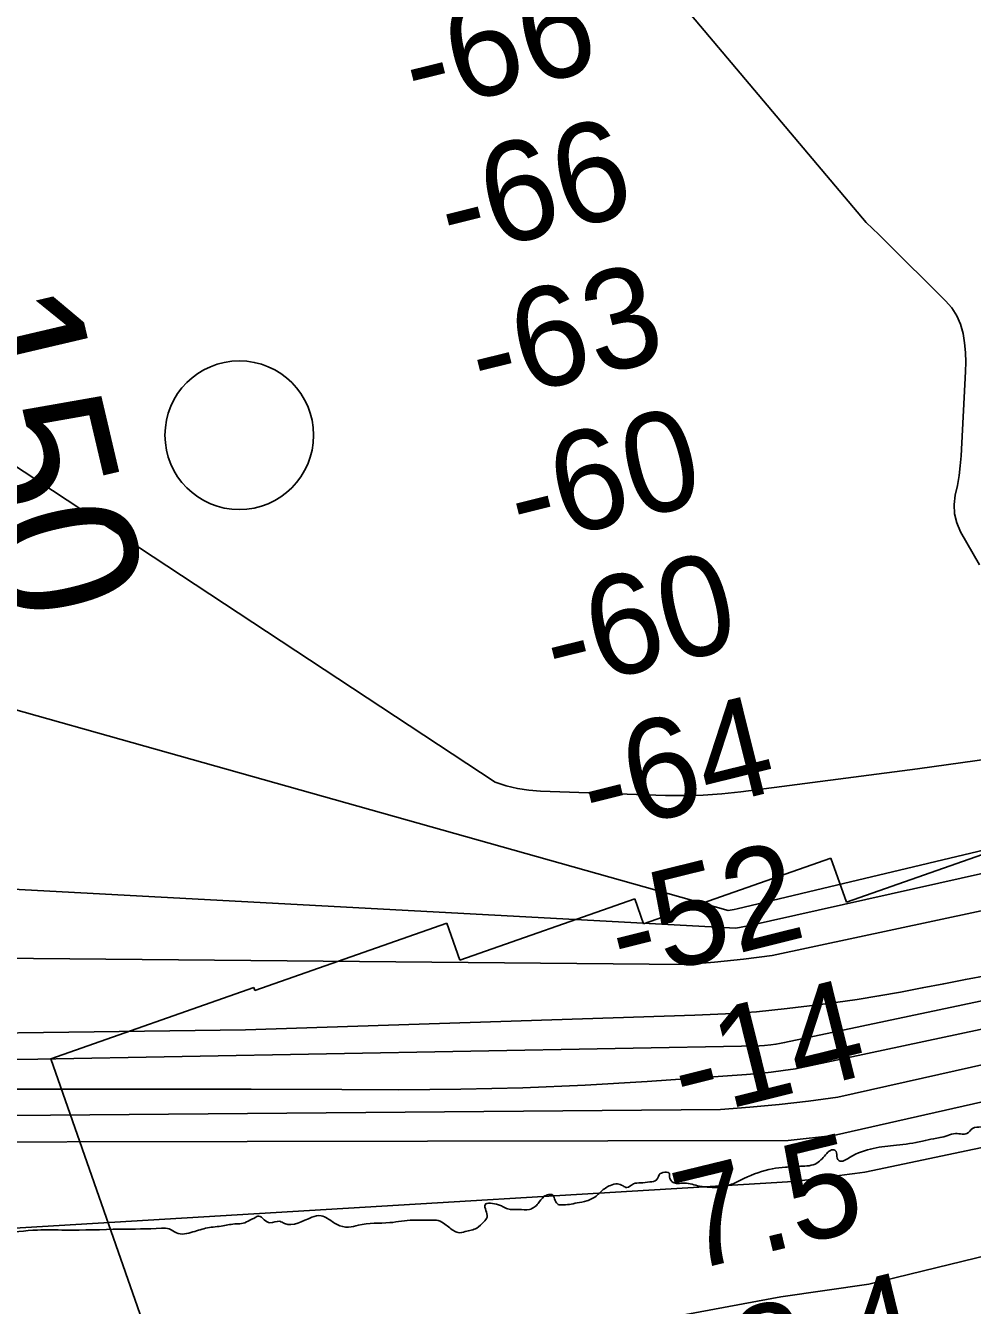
# Model space of a CAD drawing. Extents: x 3445503 to 3483459, y 540493 to 566012.
# Drawn here: x 3472232 to 3472869, y 549843 to 550704 of the extents above; entities that cross this region are included whole.
import ezdxf

# ---------------------------------------------------------------- set-up
doc = ezdxf.new("R2010")
doc.units = 0
for name, color, linetype in [('V-CHAN-NAID', 7, 'Continuous'), ('V-RIVR-EDGE', 7, 'Continuous'), ('V-RIVR-IDEN', 7, 'Continuous'), ('V-RIVR-MILE', 7, 'Continuous'), ('V-RIVR-RANG', 7, 'Continuous'), ('V-RRAP-RVMT', 7, 'Continuous'), ('V-TOPO-DPTH', 7, 'Continuous'), ('V-TOPO-MAJR', 7, 'Continuous'), ('V-TOPO-MINR', 7, 'Continuous'), ('V-TOPO-WATR', 7, 'Continuous')]:
    doc.layers.add(name, color=color, linetype=linetype)

msp = doc.modelspace()

# ---------------------------------------------------------------- linework, layer by layer
at = {"layer": 'V-RIVR-EDGE'}
msp.add_spline([(3473267.48, 550050.53), (3473262.79, 550050.71), (3473261.4, 550049.33), (3473261.38, 550045.15), (3473259.64, 550043.07), (3473258.26, 550045.51), (3473257.22, 550048.29), (3473255.14, 550048.99), (3473250.27, 550049.01), (3473240.53, 550046.25), (3473232.88, 550045.23), (3473226.97, 550045.94), (3473221.41, 550044.56), (3473208.19, 550041.11), (3473186.97, 550035.95), (3473184.19, 550035.96), (3473182.8, 550036.66), (3473178.28, 550036.67), (3473175.84, 550034.94), (3473172.71, 550034.25), (3473168.89, 550034.61), (3473164.37, 550034.27), (3473158.45, 550032.2), (3473148.02, 550030.83), (3473146.28, 550029.8), (3473145.23, 550028.41), (3473143.49, 550026.33), (3473141.4, 550025.64), (3473141.06, 550028.07), (3473137.24, 550029.47), (3473116.03, 550025.35), (3473100.03, 550021.91), (3473109.07, 550023.98), (3473098.98, 550020.53), (3473094.46, 550019.5), (3473091.68, 550019.15), (3473086.81, 550018.12), (3473072.2, 550015.38), (3473050.29, 550012.3), (3473043.68, 550010.58), (3473029.77, 550008.18), (3473028.73, 550008.88), (3473024.56, 550008.54), (3473009.6, 550004.76), (3472996.72, 549998.88), (3472990.11, 549995.07), (3472986.28, 549994.04), (3472984.9, 549996.13), (3472982.12, 549996.13), (3472970.98, 549992.34), (3472959.85, 549989.24), (3472952.2, 549988.21), (3472948.72, 549988.22), (3472946.63, 549986.49), (3472943.84, 549983.02), (3472940.36, 549980.59), (3472933.06, 549979.92), (3472926.1, 549978.2), (3472910.45, 549974.41), (3472893.06, 549969.24), (3472887.14, 549966.12), (3472884, 549963.35), (3472881.22, 549963.71), (3472874.96, 549963.03), (3472869.05, 549962), (3472865.22, 549958.53), (3472862.09, 549958.19), (3472857.57, 549958.55), (3472852.35, 549957.17), (3472847.13, 549955.79), (3472842.96, 549955.11), (3472835.31, 549953.39), (3472817.92, 549950.65), (3472786.27, 549942.39), (3472779.31, 549940.32), (3472777.92, 549942.06), (3472777.24, 549946.58), (3472775.15, 549947.63), (3472772.02, 549946.25), (3472770.98, 549945.21), (3472764.36, 549938.62), (3472753.23, 549936.56), (3472743.14, 549935.89), (3472734.45, 549934.87), (3472715.31, 549928.31), (3472708.01, 549924.85), (3472698.96, 549922.44), (3472692.36, 549922.46), (3472685.4, 549923.17), (3472675.33, 549925.28), (3472670.81, 549924.94), (3472667.68, 549925.65), (3472665.26, 549929.48), (3472664.92, 549931.91), (3472660.75, 549932.27), (3472659.01, 549931.58), (3472656.56, 549927.41), (3472652.04, 549926.03), (3472645.78, 549925.35), (3472640.91, 549924.67), (3472636.39, 549922.25), (3472633.96, 549923.3), (3472630.14, 549924.7), (3472625.61, 549923.67), (3472622.13, 549921.94), (3472616.56, 549917.08), (3472609.6, 549913.28), (3472602.99, 549911.9), (3472592.56, 549910.54), (3472589.78, 549911.24), (3472585.97, 549917.51), (3472583.88, 549917.51), (3472580.75, 549916.13), (3472576.92, 549911.62), (3472571, 549907.46), (3472563.7, 549907.48), (3472556.4, 549907.85), (3472552.92, 549909.59), (3472550.15, 549910.64), (3472541.11, 549910.66), (3472542.48, 549902.32), (3472540.38, 549899.19), (3472535.51, 549895.03), (3472527.85, 549892.62), (3472522.98, 549891.94), (3472519.86, 549893.34), (3472513.27, 549898.22), (3472508.4, 549900.32), (3472504.58, 549900.33), (3472492.76, 549900.35), (3472477.11, 549898.66), (3472455.9, 549896.97), (3472449.29, 549895.6), (3472441.65, 549897.35), (3472435.06, 549901.54), (3472430.89, 549903.29), (3472424.63, 549902.26), (3472406.19, 549898.14), (3472403.07, 549899.53), (3472396.46, 549898.51), (3472392.64, 549900.6), (3472388.83, 549903.05), (3472386.39, 549902.01), (3472382.91, 549900.28), (3472378.38, 549898.2), (3472373.86, 549897.87), (3472364.82, 549896.5), (3472354.39, 549895.13), (3472344.65, 549892.38), (3472333.52, 549891.71), (3472328.66, 549894.5), (3472323.45, 549894.86), (3472295.64, 549894.24), (3472258.79, 549893.63), (3472240.02, 549893.68), (3472214.98, 549891.31), (3472201.42, 549889.95), (3472194.46, 549888.58), (3472186.47, 549888.95), (3472180.57, 549892.78), (3472173.97, 549894.19), (3472164.58, 549894.21), (3472142.68, 549894.62), (3472134.68, 549893.94), (3472115.91, 549892.25), (3472099.57, 549892.64), (3472079.06, 549891.99), (3472074.2, 549895.48), (3472067.95, 549898.62), (3472059.26, 549898.65), (3472042.57, 549898.34), (3472034.23, 549898.36), (3472025.19, 549899.77), (3472021.37, 549901.17), (3472015.12, 549901.54), (3472000.87, 549902.27), (3471998.43, 549901.58), (3471996.34, 549899.15), (3471992.86, 549897.42), (3471989.74, 549901.6), (3471986.96, 549901.95), (3471978.96, 549901.63), (3471972.7, 549900.6), (3471966.79, 549900.61), (3471957.4, 549898.55), (3471951.84, 549897.52), (3471943.49, 549896.85), (3471929.59, 549896.19), (3471925.41, 549895.5), (3471920.54, 549892.38), (3471918.79, 549889.26), (3471914.62, 549887.18), (3471909.05, 549887.2), (3471906.28, 549890.33), (3471902.12, 549893.82), (3471877.78, 549893.53), (3471874.99, 549890.06), (3471872.21, 549887.98), (3471868.38, 549886.95), (3471863.86, 549887.31), (3471857.96, 549889.76), (3471851.7, 549890.47), (3471841.27, 549889.45), (3471833.28, 549889.47), (3471826.33, 549891.92), (3471821.47, 549894.37), (3471818.68, 549892.98), (3471815.55, 549891.6), (3471812.42, 549888.48), (3471807.88, 549883.62), (3471803.7, 549879.81), (3471798.83, 549879.13), (3471794.67, 549881.92), (3471789.48, 549891.32), (3471784.27, 549895.5), (3471778.72, 549896.56), (3471759.95, 549900.43), (3471750.92, 549904.27), (3471745.71, 549905.33), (3471738.4, 549900.48), (3471734.92, 549898.06), (3471725.87, 549896.34), (3471684.85, 549896.44)], degree=3, dxfattribs=at)
at = {"layer": 'V-RIVR-MILE'}
msp.add_circle((3472375.81, 550428.15), 50, dxfattribs=at)
at = {"layer": 'V-RRAP-RVMT'}
for p, q in [((3472784.2, 550114.21), (3472906.99, 550157.21)), ((3472647.79, 550099.5), (3472773.84, 550143.76)), ((3472773.84, 550143.76), (3472784.2, 550114.21)), ((3472524.26, 550075.16), (3472641.82, 550116.34)), ((3472641.82, 550116.34), (3472647.79, 550099.5)), ((3472386.21, 550054.83), (3472515.5, 550100.12)), ((3472515.5, 550100.12), (3472524.26, 550075.16)), ((3472249.04, 550008.89), (3472385.49, 550056.81)), ((3472385.49, 550056.81), (3472386.21, 550054.83)), ((3472416.68, 549530.16), (3472249.04, 550008.89))]:
    msp.add_line(p, q, dxfattribs=at)
at = {"layer": 'V-TOPO-DPTH'}
for points in [[(3471527.3, 550203.44), (3471721.65, 550155.04), (3471725.84, 550154.05), (3471730.04, 550153.13), (3471734.26, 550152.32), (3471738.49, 550151.57), (3471742.74, 550150.91), (3471747, 550150.29), (3471751.26, 550149.73), (3471755.53, 550149.21), (3471756.08, 550149.15), (3471760.62, 550148.63), (3471765.17, 550148.11), (3471769.71, 550147.59), (3471774.26, 550147.06), (3472709.72, 550096.65), (3472718.14, 550098.12), (3473740.18, 550326.75)], [(3473740.18, 550326.75), (3472718.14, 550098.12), (3472709.72, 550096.65), (3471774.26, 550147.06), (3471769.71, 550147.59), (3471765.17, 550148.11), (3471760.62, 550148.63), (3471756.08, 550149.15), (3471755.53, 550149.21), (3471751.26, 550149.73), (3471747, 550150.29), (3471742.74, 550150.91), (3471738.49, 550151.57), (3471734.26, 550152.32), (3471730.04, 550153.13), (3471725.84, 550154.05), (3471721.65, 550155.04), (3471527.3, 550203.44)], [(3473778.31, 550301.21), (3472734.35, 550078.36), (3472714.95, 550075.72), (3472695.49, 550073.71), (3472675.97, 550072.12), (3471798.63, 550080.29), (3471782.69, 550082.03), (3471766.76, 550083.77), (3471750.81, 550085.5), (3471734.87, 550087.21), (3471589.23, 550102.82), (3471500.51, 550112.74)], [(3473778.31, 550301.21), (3472734.35, 550078.36), (3472714.95, 550075.72), (3472695.49, 550073.71), (3472675.97, 550072.12), (3471798.63, 550080.29), (3471782.69, 550082.03), (3471766.76, 550083.77), (3471750.81, 550085.5), (3471734.87, 550087.21), (3471589.23, 550102.82), (3471500.51, 550112.74)], [(3473773.74, 550257.36), (3472893.34, 550067.65), (3472878.79, 550064.94), (3472864.25, 550062.17), (3472849.72, 550059.34), (3472835.21, 550056.47), (3472820.67, 550053.69), (3472806.11, 550051.1), (3472791.5, 550048.78), (3472776.86, 550046.65), (3472764.97, 550045.04), (3472744.33, 550042.55), (3472723.66, 550040.49), (3472702.93, 550039.07), (3472682.17, 550038.08), (3472379.93, 550028.25), (3472074.04, 550024.36)], [(3472074.04, 550024.36), (3472379.93, 550028.25), (3472682.17, 550038.08), (3472702.93, 550039.07), (3472723.66, 550040.49), (3472744.33, 550042.55), (3472764.97, 550045.04), (3472776.86, 550046.65), (3472791.5, 550048.78), (3472806.11, 550051.1), (3472820.67, 550053.69), (3472835.21, 550056.47), (3472849.72, 550059.34), (3472864.25, 550062.17), (3472878.79, 550064.94), (3472893.34, 550067.65), (3473773.74, 550257.36)], [(3472200.98, 549988.31), (3472261.93, 549988.39), (3472322.88, 549988.4), (3472383.83, 549988.31), (3472444.78, 549988.15), (3472483.03, 549988.02), (3472524.84, 549988.34), (3472566.63, 549989.28), (3472608.39, 549991.14), (3472650.13, 549993.61), (3472716.98, 549998.31), (3472725.27, 549999.01), (3472733.53, 549999.86), (3472741.77, 550000.93), (3472749.99, 550002.15), (3473790.16, 550223.51)], [(3473790.16, 550223.51), (3472749.99, 550002.15), (3472741.77, 550000.93), (3472733.53, 549999.86), (3472725.27, 549999.01), (3472716.98, 549998.31), (3472650.13, 549993.61), (3472608.39, 549991.14), (3472566.63, 549989.28), (3472524.84, 549988.34), (3472483.03, 549988.02), (3472444.78, 549988.15), (3472383.83, 549988.31), (3472322.88, 549988.4), (3472261.93, 549988.39), (3472200.98, 549988.31)], [(3470946.4, 549853.99), (3471729.66, 549947.71), (3471734.85, 549948.49), (3471740.05, 549949.26), (3471745.25, 549949.99), (3471750.45, 549950.7), (3471756.33, 549951.49), (3471758.6, 549951.75), (3471760.87, 549951.94), (3471765.44, 549952.1), (3471770.01, 549952.1), (3471770.95, 549952.09), (3471773, 549952.07), (3471774.68, 549952.01), (3472745.03, 549953.83), (3472775.52, 549957.22), (3473815.22, 550192.33)], [(3473815.22, 550192.33), (3472775.52, 549957.22), (3472745.03, 549953.83), (3471774.68, 549952.01), (3471773, 549952.07), (3471770.95, 549952.09), (3471770.01, 549952.1), (3471765.44, 549952.1), (3471760.87, 549951.94), (3471758.6, 549951.75), (3471756.33, 549951.49), (3471750.45, 549950.7), (3471745.25, 549949.99), (3471740.05, 549949.26), (3471734.85, 549948.49), (3471729.66, 549947.71), (3470946.4, 549853.99)], [(3470939.3, 549539.25), (3471769.26, 549665.38), (3471777.21, 549668.18), (3471785.28, 549670.63), (3471793.42, 549672.85), (3472740.02, 549848.75), (3472769.67, 549852.91), (3472799.28, 549857.36), (3473865.35, 550116.97)]]:
    msp.add_lwpolyline(points, dxfattribs=at)
at = {"layer": 'V-TOPO-MAJR'}
msp.add_lwpolyline([(3471199.79, 550599.19), (3471655.04, 550418.7), (3471730.39, 550395.7), (3471744.71, 550390.98), (3471758.88, 550385.86), (3471772.81, 550380.13), (3471786.58, 550373.99), (3471808.04, 550363.87), (3471810.97, 550362.49), (3471813.9, 550361.1), (3471816.82, 550359.72), (3471819.75, 550358.34), (3471822.67, 550356.94), (3472704.63, 550108.54), (3472708.74, 550109.25), (3472710.78, 550109.72), (3473738.5, 550354.33)], dxfattribs=at)
at = {"layer": 'V-TOPO-MINR'}
for points in [[(3472667.99, 550724.88), (3472797.45, 550571.12), (3472801.71, 550567.17), (3472805.91, 550563.15), (3472810.07, 550559.09), (3472850.96, 550518.56), (3472855.04, 550513.69), (3472858.46, 550508.48), (3472860.89, 550502.73), (3472862.66, 550496.63), (3472863.66, 550490.23), (3472864.34, 550483.81), (3472864.54, 550477.35), (3472864.43, 550470.87), (3472861.34, 550414.28), (3472860.79, 550407.61), (3472860, 550400.98), (3472858.85, 550394.4), (3472857.46, 550387.86), (3472856.68, 550381.46), (3472856.85, 550375.19), (3472858.44, 550369.13), (3472860.97, 550363.2), (3472873.66, 550341.05)], [(3471751.03, 550719.51), (3472547.98, 550194.83), (3472555.42, 550192.42), (3472562.96, 550190.52), (3472570.65, 550189.37), (3472578.44, 550188.72), (3472662.47, 550185.96), (3472675.18, 550185.85), (3472687.86, 550186.15), (3472700.52, 550187.06), (3472713.16, 550188.38), (3472831.96, 550203.7), (3472881.81, 550210.78)], [(3471527.3, 550203.44), (3471721.65, 550155.04), (3471725.84, 550154.05), (3471730.04, 550153.13), (3471734.26, 550152.32), (3471738.49, 550151.57), (3471742.74, 550150.91), (3471747, 550150.29), (3471751.26, 550149.73), (3471755.53, 550149.21), (3471756.08, 550149.15), (3471760.62, 550148.63), (3471765.17, 550148.11), (3471769.71, 550147.59), (3471774.26, 550147.06), (3472709.72, 550096.65), (3472718.14, 550098.12), (3473740.18, 550326.75)], [(3471500.51, 550112.74), (3471589.23, 550102.82), (3471734.87, 550087.21), (3471750.81, 550085.5), (3471766.76, 550083.77), (3471782.69, 550082.03), (3471798.63, 550080.29), (3472675.97, 550072.12), (3472695.49, 550073.71), (3472714.95, 550075.72), (3472734.35, 550078.36), (3473778.31, 550301.21)], [(3472074.04, 550024.36), (3472379.93, 550028.25), (3472682.17, 550038.08), (3472702.93, 550039.07), (3472723.66, 550040.49), (3472744.33, 550042.55), (3472764.97, 550045.04), (3472776.86, 550046.65), (3472791.5, 550048.78), (3472806.11, 550051.1), (3472820.67, 550053.69), (3472835.21, 550056.47), (3472849.72, 550059.34), (3472864.25, 550062.17), (3472878.79, 550064.94), (3472893.34, 550067.65), (3473773.74, 550257.36)], [(3471508.55, 550019.96), (3471595.21, 550015.82), (3471725.59, 550010.46), (3471747.11, 550009.68), (3471768.62, 550009.03), (3471790.14, 550008.59), (3471811.67, 550008.28), (3471925.83, 550007.16), (3472004.43, 550006.72), (3472083.04, 550006.73), (3472161.64, 550007.42), (3472240.23, 550008.54), (3472725.81, 550017.57), (3472729.1, 550017.71), (3472733.32, 550018.13), (3472736.82, 550018.65), (3472739.13, 550019.1), (3472742.6, 550019.75), (3473765.95, 550235.81)], [(3470947.91, 549982.77), (3471716.43, 549971.19), (3471742.99, 549970.84), (3471769.56, 549970.54), (3471796.13, 549970.33), (3471822.7, 549970.18), (3471849.27, 549970.05), (3471875.84, 549969.88), (3471902.41, 549969.65), (3471928.98, 549969.38), (3471947.57, 549969.17), (3471983.43, 549968.66), (3472699.43, 549974.82), (3472719.23, 549976.22), (3472738.99, 549978), (3472758.69, 549980.33), (3472778.35, 549983.04), (3473872.39, 550228.36)], [(3472200.98, 549988.31), (3472261.93, 549988.39), (3472322.88, 549988.4), (3472383.83, 549988.31), (3472444.78, 549988.15), (3472483.03, 549988.02), (3472524.84, 549988.34), (3472566.63, 549989.28), (3472608.39, 549991.14), (3472650.13, 549993.61), (3472716.98, 549998.31), (3472725.27, 549999.01), (3472733.53, 549999.86), (3472741.77, 550000.93), (3472749.99, 550002.15), (3473790.16, 550223.51)], [(3471043.28, 549696.38), (3471763.09, 549868.88), (3471772.07, 549869.58), (3471781.05, 549870.15), (3471790.04, 549870.63), (3471844.29, 549873.13), (3471880.41, 549874.87), (3471916.52, 549876.7), (3471952.62, 549878.69), (3471988.72, 549880.77), (3472737.47, 549925.56), (3472744.5, 549926.07), (3472751.52, 549926.69), (3472758.53, 549927.48), (3472765.52, 549928.38), (3472772.64, 549929.39), (3472776.06, 549929.87), (3472779.49, 549930.36), (3472782.92, 549930.84), (3472786.34, 549931.32), (3472789.77, 549931.8), (3472793.2, 549932.25), (3472796.63, 549932.69), (3473826.3, 550149.13)], [(3470939.3, 549539.25), (3471769.26, 549665.38), (3471777.21, 549668.18), (3471785.28, 549670.63), (3471793.42, 549672.85), (3472740.02, 549848.75), (3472769.67, 549852.91), (3472799.28, 549857.36), (3473865.35, 550116.97)]]:
    msp.add_lwpolyline(points, dxfattribs=at)
at = {"layer": 'V-TOPO-WATR'}
msp.add_lwpolyline([(3470946.4, 549853.99), (3471729.66, 549947.71), (3471734.85, 549948.49), (3471740.05, 549949.26), (3471745.25, 549949.99), (3471750.45, 549950.7), (3471756.33, 549951.49), (3471758.6, 549951.75), (3471760.87, 549951.94), (3471765.44, 549952.1), (3471770.01, 549952.1), (3471770.95, 549952.09), (3471773, 549952.07), (3471774.68, 549952.01), (3472745.03, 549953.83), (3472775.52, 549957.22), (3473815.22, 550192.33)], dxfattribs=at)

# ---------------------------------------------------------------- texts
at = {"layer": 'V-CHAN-NAID'}
msp.add_text('JOHN W. STONE (150.1)', height=100, rotation=299.61286, dxfattribs=at).set_placement((3472611.5, 551591.42))
at = {"layer": 'V-RIVR-IDEN'}
msp.add_text('150', height=100, rotation=283.21921, dxfattribs=at).set_placement((3472166.14, 550514.83))
at = {"layer": 'V-RIVR-RANG'}
for s, rotation, p in [('-66', 13.96028, (3472494.46, 550643.96)), ('-66', 13.96028, (3472518.35, 550546.85)), ('-63', 13.96028, (3472539.16, 550448.98)), ('-60', 13.96028, (3472565.35, 550352.45)), ('-60', 13.96028, (3472589.23, 550255.34)), ('-64', 13.96028, (3472614.14, 550158.49)), ('-52', 13.96028, (3472633.16, 550060.18)), ('-14', 13.96028, (3472675.22, 549967.59)), ('7.5', 13.67833, (3472678.37, 549865.76)), ('13.4', 13.67833, (3472669.96, 549760.8))]:
    msp.add_text(s, height=67, rotation=rotation, dxfattribs=at).set_placement(p)

doc.saveas('drawing.dxf')
